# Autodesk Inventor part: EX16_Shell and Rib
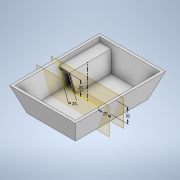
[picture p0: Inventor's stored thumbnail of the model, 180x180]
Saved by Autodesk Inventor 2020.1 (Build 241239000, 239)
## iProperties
Created: 2019-10
Part Number: EX16_Shell and Rib
Material: Generic
Document SubType Name: Modeling
Designer: Synergysoft Dell02
Density: 1 g/cm^3
Appearance: Default
Author: Synergysoft Dell02
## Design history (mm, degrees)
sketch "Sketch1"
  geometry: L1 (50, -75)-(-50, -75); L2 (-50, -75)-(-50, 75); L3 (-50, 75)-(50, 75); L4 (50, 75)-(50, -75); L5 (50, -75)-(-50, 75); L6 (-50, -75)-(50, 75); 1 further point
  constraints: 12 end point, 2 midpoint, 2 parallel, 1 horizontal, 1 perpendicular
  dimensions: "d0" = 100 distance of L2.end L3.end; "d1" = 150 distance of L1.end L2.end
extrude "Extrusion1" new body sketch "Sketch1" distance "d2" = 50; taper "d3" = 20 deg
shell "Shell1" dims "d4" = 5, "d27" = 10
feature "Rib2" dims "d15" = 5, "d16" = 1, "d17" = 0, "d18" = 0, "d19" = 1, "d20" = 1
feature "Rib4" dims "d34" = 10, "d35" = 10, "d36" = 0, "d37" = 0, "d38" = 1, "d39" = 1
workplane "Work Plane3"
sketch "Sketch3"
  geometry: L1 (23.319, 10)-(59.238, 40) reference; 1 further point
feature "Rib5" sketch "Sketch3" dims "d41" = 5, "d42" = 20, "d43" = 0, "d44" = 0, "d45" = 1, "d46" = 1
body "Solid1"
sketch "Sketch2"
  geometry: L1 (-48.319, 10)-(-62.878, 50) reference; L2 (48.319, 10)-(-48.319, 10) reference; L3 (48.319, 10)-(62.878, 50) reference; L4 (-59.238, 40)-(-37.954, 40); L5 (-37.954, 40)-(-27.035, 10); L6 (0, 0)-(0, 79.65); L7 (23.319, 10)-(59.238, 40)
  constraints: 8 end point, 4 point on line, 1 horizontal, 1 parallel, 1 vertical
  dimensions: "d7" = 30 distance between parallel lines of L2 L4; "d8" = 20 distance between parallel lines of L5 L1; "d32" = 25 distance of L2.start L7.start; "d33" = 30 distance from line of L7.end L2
